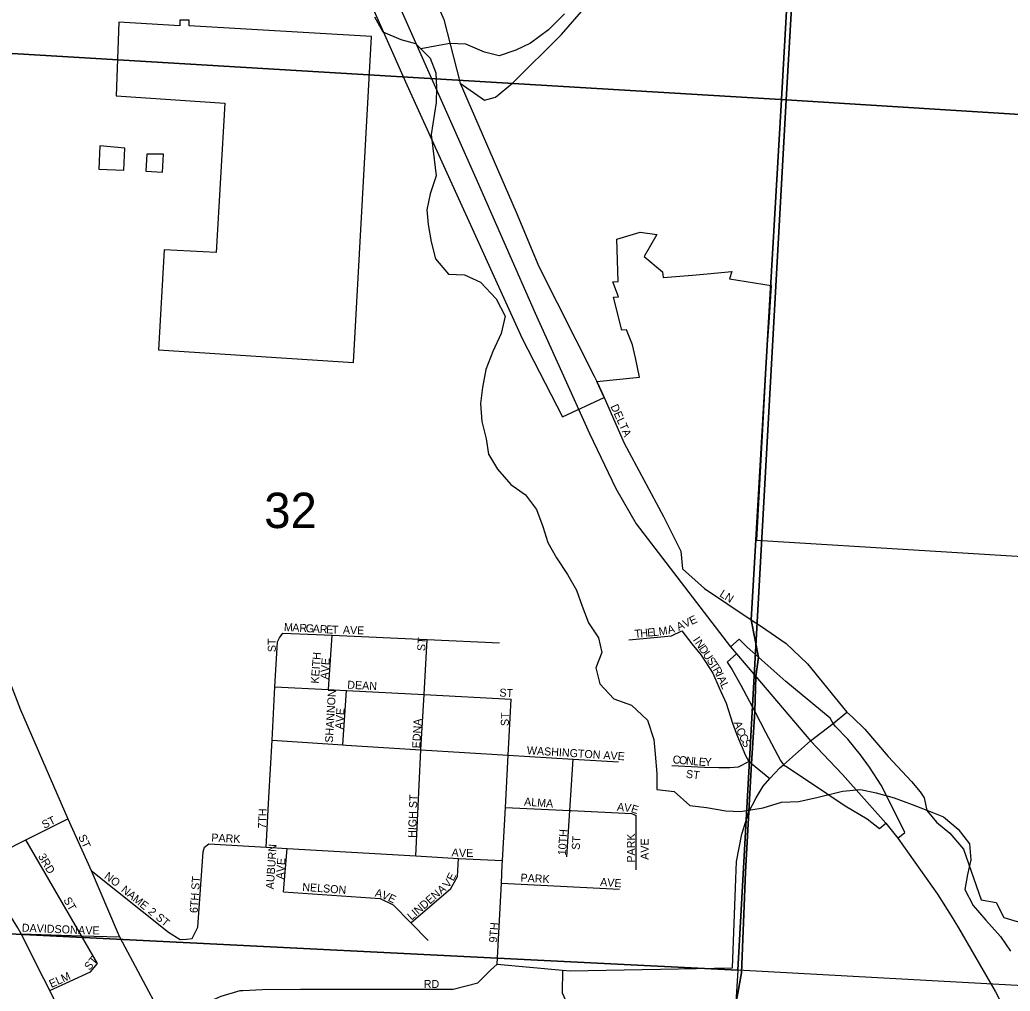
# Model space of a CAD drawing. Extents: x 1949938.81 to 1949945.61, y 152207.65 to 152214.09.
# Drawn here: x 1949940.427 to 1949941.599, y 152209.158 to 152210.308 of the extents above; entities that cross this region are included whole.
import ezdxf

# ---------------------------------------------------------------- set-up
doc = ezdxf.new("R2010")
doc.units = 0
for name, color, linetype in [('GM_X_City_Street', 7, 'Continuous'), ('GM_X_City_Street_Text', 7, 'Continuous'), ('GM_X_Corporation', 7, 'Continuous'), ('GM_X_County_Road', 7, 'Continuous'), ('GM_X_Interchange_Ramps', 7, 'Continuous'), ('GM_X_Minor_River', 7, 'Continuous'), ('GM_X_Section', 7, 'Continuous'), ('GM_X_Section_Text', 7, 'Continuous'), ('GM_X_Township', 7, 'Continuous'), ('GM_X_Township_Road', 7, 'Continuous'), ('GM_X_US_Route', 7, 'Continuous')]:
    doc.layers.add(name, color=color, linetype=linetype)

msp = doc.modelspace()

# ---------------------------------------------------------------- linework, layer by layer
at = {"layer": 'GM_X_City_Street'}
for points in [[(1949941.1155, 152209.8678), (1949941.1187, 152209.8607), (1949941.1424, 152209.8068), (1949941.1891, 152209.72), (1949941.2095, 152209.679), (1949941.2114, 152209.6583), (1949941.2375, 152209.6347), (1949941.2927, 152209.598), (1949941.3038, 152209.5906), (1949941.3341, 152209.5697), (1949941.3595, 152209.5458), (1949941.4062, 152209.4887)], [(1949940.3073, 152209.828), (1949940.3099, 152209.8198), (1949940.3687, 152209.6481), (1949940.3953, 152209.5754), (1949940.428, 152209.4915), (1949940.4841, 152209.3624), (1949940.5115, 152209.3013), (1949940.5424, 152209.2289)], [(1949940.722, 152209.3876), (1949940.722, 152209.3877), (1949940.7258, 152209.4553), (1949940.7292, 152209.5187), (1949940.7322, 152209.5719), (1949940.7345, 152209.5764), (1949940.7384, 152209.5821)], [(1949940.7384, 152209.5821), (1949940.7778, 152209.5803), (1949940.7778, 152209.5803)], [(1949941.1694, 152209.5761), (1949941.1986, 152209.5789), (1949941.2107, 152209.5846)], [(1949941.2107, 152209.5846), (1949941.2225, 152209.5695), (1949941.2336, 152209.5561), (1949941.2475, 152209.5346), (1949941.2548, 152209.5174), (1949941.2631, 152209.4991), (1949941.2707, 152209.4754), (1949941.2757, 152209.4616), (1949941.286, 152209.4373), (1949941.2901, 152209.4302), (1949941.293, 152209.4279), (1949941.3147, 152209.4102)], [(1949940.7778, 152209.5803), (1949940.7971, 152209.5795), (1949940.9092, 152209.5745), (1949940.9949, 152209.5706)], [(1949940.7924, 152209.5154), (1949940.7971, 152209.5795)], [(1949940.902, 152209.444), (1949940.9056, 152209.5094), (1949940.9092, 152209.5745)], [(1949941.1481, 152209.5741), (1949941.1694, 152209.5761)], [(1949941.4126, 152209.4825), (1949941.4273, 152209.4684), (1949941.4548, 152209.436), (1949941.4824, 152209.4065), (1949941.4928, 152209.3941), (1949941.4976, 152209.3871), (1949941.5005, 152209.3722), (1949941.5121, 152209.3585), (1949941.528, 152209.3455), (1949941.544, 152209.3266), (1949941.5648, 152209.2665), (1949941.5827, 152209.2632), (1949941.592, 152209.2455), (1949941.6075, 152209.2407), (1949941.6263, 152209.2428), (1949941.6379, 152209.251), (1949941.6564, 152209.2608), (1949941.6746, 152209.2817), (1949941.6788, 152209.3083), (1949941.6833, 152209.3542), (1949941.689, 152209.3706), (1949941.7068, 152209.4032), (1949941.7925, 152209.5244), (1949941.7945, 152209.5273)], [(1949940.7292, 152209.5187), (1949940.7924, 152209.5154), (1949940.7992, 152209.515)], [(1949940.7992, 152209.515), (1949940.7992, 152209.515), (1949940.8137, 152209.5143), (1949940.9056, 152209.5094), (1949941.0089, 152209.5039)], [(1949940.8096, 152209.4499), (1949940.8137, 152209.5143)], [(1949940.9983, 152209.3079), (1949940.9986, 152209.3132), (1949941.002, 152209.3759), (1949941.0053, 152209.4377), (1949941.0089, 152209.5039)], [(1949941.3897, 152209.4752), (1949941.4062, 152209.4887), (1949941.4126, 152209.4825)], [(1949941.3698, 152209.4596), (1949941.3897, 152209.4752)], [(1949940.7258, 152209.4553), (1949940.8096, 152209.4499), (1949940.8134, 152209.4497), (1949940.8136, 152209.4497)], [(1949941.2748, 152209.2912), (1949941.2756, 152209.312), (1949941.2818, 152209.3443), (1949941.2899, 152209.3706), (1949941.2986, 152209.3871), (1949941.3071, 152209.4008), (1949941.3147, 152209.4102), (1949941.3267, 152209.4227), (1949941.331, 152209.4264), (1949941.3632, 152209.4545), (1949941.3698, 152209.4596)], [(1949940.8136, 152209.4497), (1949940.902, 152209.444), (1949941.0053, 152209.4377), (1949941.082, 152209.4331), (1949941.1358, 152209.4298)], [(1949940.8961, 152209.3185), (1949940.902, 152209.444)], [(1949941.0745, 152209.3173), (1949941.078, 152209.3723), (1949941.082, 152209.4331)], [(1949941.2545, 152209.4232), (1949941.2675, 152209.4231), (1949941.2779, 152209.424), (1949941.2901, 152209.4302)], [(1949941.1988, 152209.4255), (1949941.2377, 152209.4233), (1949941.2545, 152209.4232)], [(1949940.7188, 152209.3287), (1949940.722, 152209.3876)], [(1949941.002, 152209.3759), (1949941.078, 152209.3723), (1949941.0796, 152209.3722), (1949941.0796, 152209.3722)], [(1949941.0796, 152209.3722), (1949941.1513, 152209.3688), (1949941.1566, 152209.3661)], [(1949940.3786, 152209.3094), (1949940.4345, 152209.3375), (1949940.4841, 152209.3624)], [(1949941.1566, 152209.3019), (1949941.1566, 152209.3661)], [(1949940.5002, 152209.224), (1949940.4345, 152209.3375)], [(1949940.6247, 152209.2201), (1949940.6312, 152209.2208), (1949940.6378, 152209.234), (1949940.6442, 152209.3233), (1949940.6458, 152209.3289)], [(1949940.6458, 152209.3289), (1949940.6508, 152209.3327), (1949940.7188, 152209.3287), (1949940.7435, 152209.3273), (1949940.8961, 152209.3185), (1949940.9463, 152209.3156), (1949940.9986, 152209.3132)], [(1949940.7395, 152209.2761), (1949940.7435, 152209.3273)], [(1949940.8899, 152209.2393), (1949940.9375, 152209.2798), (1949940.9453, 152209.2942), (1949940.9463, 152209.3156)], [(1949940.4828, 152209.1185), (1949940.4627, 152209.1592), (1949940.4558, 152209.1732), (1949940.4287, 152209.2261), (1949940.4251, 152209.2332), (1949940.3975, 152209.2768), (1949940.3786, 152209.3094)], [(1949940.5115, 152209.3013), (1949940.6032, 152209.2284), (1949940.6171, 152209.2195), (1949940.6247, 152209.2201)], [(1949940.992, 152209.1902), (1949940.9972, 152209.2864), (1949940.9983, 152209.3079), (1949940.9983, 152209.3079)], [(1949940.6913, 152209.1593), (1949940.7145, 152209.1603), (1949940.7595, 152209.1607), (1949940.9401, 152209.1606), (1949940.9693, 152209.1682), (1949940.9844, 152209.1834), (1949940.992, 152209.1902), (1949941.0694, 152209.1834), (1949941.0787, 152209.1826), (1949941.2707, 152209.1859), (1949941.2748, 152209.2912)], [(1949940.9972, 152209.2864), (1949941.137, 152209.2793)], [(1949940.7395, 152209.2761), (1949940.8539, 152209.2679), (1949940.869, 152209.2605), (1949940.8899, 152209.2393), (1949940.9106, 152209.2182)], [(1949940.4287, 152209.2261), (1949940.5002, 152209.224), (1949940.5451, 152209.2227)], [(1949940.5193, 152209.191), (1949940.5002, 152209.224)], [(1949940.5424, 152209.2289), (1949940.5451, 152209.2227), (1949940.5948, 152209.1297), (1949940.5981, 152209.1219)], [(1949940.4627, 152209.1592), (1949940.5109, 152209.1812), (1949940.5193, 152209.191)], [(1949941.0694, 152209.1834), (1949941.0691, 152209.1566), (1949941.0772, 152209.1391), (1949941.1035, 152209.1159), (1949941.1339, 152209.0939), (1949941.1516, 152209.0857), (1949941.1711, 152209.0843), (1949941.1873, 152209.0832), (1949941.2206, 152209.0808), (1949941.2628, 152209.0777), (1949941.2661, 152209.0775)], [(1949940.5981, 152209.1219), (1949940.627, 152209.1354), (1949940.6657, 152209.1525), (1949940.6882, 152209.1592), (1949940.6913, 152209.1593)]]:
    msp.add_lwpolyline(points, dxfattribs=at)
at = {"layer": 'GM_X_Corporation'}
msp.add_lwpolyline([(1949940.8339, 152210.3468), (1949940.8851, 152210.231), (1949941.0217, 152209.9309), (1949941.0697, 152209.8379), (1949941.1187, 152209.8607), (1949941.1101, 152209.88), (1949941.1608, 152209.8849), (1949941.1558, 152209.9078), (1949941.1522, 152209.9233), (1949941.1454, 152209.941), (1949941.1397, 152209.9406), (1949941.13, 152209.9796), (1949941.1357, 152209.98), (1949941.1289, 152209.9978), (1949941.1355, 152209.9983), (1949941.1338, 152210.0482), (1949941.1615, 152210.0567), (1949941.1812, 152210.0539), (1949941.1661, 152210.0278), (1949941.188, 152210.0094), (1949941.1885, 152210.0028), (1949941.2234, 152210.0058), (1949941.2406, 152210.0073), (1949941.2698, 152210.0099), (1949941.267, 152210.0014), (1949941.3166, 152209.9936), (1949941.3139, 152209.955), (1949941.3114, 152209.9182), (1949941.299, 152209.692), (1949941.7101, 152209.6669)], dxfattribs=at)
for points in [[(1949940.5446, 152210.3052), (1949940.5412, 152210.218), (1949940.67, 152210.209), (1949940.6596, 152210.0323), (1949940.5979, 152210.0357), (1949940.5915, 152209.9173), (1949940.8223, 152209.9024), (1949940.8435, 152210.2879), (1949940.6278, 152210.3005), (1949940.6275, 152210.3074), (1949940.6166, 152210.3075), (1949940.6165, 152210.3008)], [(1949940.5219, 152210.1588), (1949940.5207, 152210.1311), (1949940.5502, 152210.13), (1949940.5517, 152210.1561)], [(1949940.5764, 152210.1289), (1949940.5962, 152210.1274), (1949940.5973, 152210.149), (1949940.5775, 152210.149)]]:
    msp.add_lwpolyline(points, close=True, dxfattribs=at)
at = {"layer": 'GM_X_County_Road'}
for points in [[(1949940.6238, 152210.9905), (1949940.7663, 152210.6357), (1949940.884, 152210.3789), (1949940.9129, 152210.3457), (1949940.9292, 152210.3083), (1949940.9485, 152210.2329)], [(1949940.9485, 152210.2329), (1949941.0146, 152210.0802), (1949941.0415, 152210.0159), (1949941.1071, 152209.886)], [(1949941.1071, 152209.886), (1949941.1101, 152209.88), (1949941.1155, 152209.8678)]]:
    msp.add_lwpolyline(points, dxfattribs=at)
at = {"layer": 'GM_X_Interchange_Ramps'}
for points in [[(1949941.3897, 152209.4752), (1949941.3861, 152209.4813), (1949941.334, 152209.5247), (1949941.3053, 152209.5502), (1949941.3013, 152209.5538), (1949941.2882, 152209.5653), (1949941.2787, 152209.5748), (1949941.2684, 152209.5658)], [(1949941.2755, 152209.5576), (1949941.2643, 152209.5479), (1949941.27, 152209.5396), (1949941.2805, 152209.5207), (1949941.2971, 152209.4892), (1949941.3099, 152209.4648), (1949941.3274, 152209.4314), (1949941.331, 152209.4264)], [(1949941.4662, 152209.3396), (1949941.4746, 152209.3462), (1949941.4638, 152209.3687), (1949941.4467, 152209.4021), (1949941.4328, 152209.4233), (1949941.4221, 152209.4382), (1949941.4071, 152209.4565), (1949941.3926, 152209.4716), (1949941.3897, 152209.4752)], [(1949941.331, 152209.4264), (1949941.3359, 152209.4235), (1949941.3825, 152209.3925), (1949941.4042, 152209.3777), (1949941.43, 152209.3624), (1949941.4447, 152209.3508), (1949941.452, 152209.3572)]]:
    msp.add_lwpolyline(points, dxfattribs=at)
at = {"layer": 'GM_X_Minor_River'}
for points in [[(1949940.8471, 152210.3113), (1949940.8569, 152210.2937), (1949940.878, 152210.2845), (1949940.8954, 152210.2799), (1949940.9128, 152210.2624), (1949940.9195, 152210.2449), (1949940.9202, 152210.2274), (1949940.9201, 152210.2099), (1949940.9139, 152210.1719), (1949940.9176, 152210.143), (1949940.9198, 152210.1232), (1949940.9129, 152210.1019), (1949940.909, 152210.0829), (1949940.9105, 152210.0654), (1949940.9142, 152210.0449), (1949940.9194, 152210.0251), (1949940.9345, 152210.0068), (1949940.9534, 152210.006), (1949940.9723, 152209.9975), (1949940.9911, 152209.9777), (1949941.0017, 152209.9571), (1949940.997, 152209.9366), (1949940.9871, 152209.9154), (1949940.9787, 152209.8941), (1949940.9748, 152209.8728), (1949940.9725, 152209.8538), (1949940.9739, 152209.8325), (1949940.9791, 152209.812), (1949940.9821, 152209.7937), (1949940.9926, 152209.7762), (1949941.0084, 152209.7579), (1949941.0258, 152209.7457), (1949941.0386, 152209.7282), (1949941.0461, 152209.7084), (1949941.0521, 152209.6894), (1949941.0626, 152209.6711), (1949941.0754, 152209.6513), (1949941.0859, 152209.633), (1949941.0926, 152209.614), (1949941.1001, 152209.5942), (1949941.1122, 152209.5767), (1949941.1159, 152209.5592), (1949941.109, 152209.541), (1949941.1135, 152209.522), (1949941.1301, 152209.5044), (1949941.1512, 152209.4968), (1949941.1701, 152209.4792), (1949941.1776, 152209.4564), (1949941.179, 152209.4389), (1949941.1812, 152209.4161), (1949941.1811, 152209.3971), (1949941.2016, 152209.3948), (1949941.2204, 152209.378), (1949941.2401, 152209.3756), (1949941.2628, 152209.3718), (1949941.2802, 152209.3709), (1949941.3068, 152209.3754), (1949941.3288, 152209.3822), (1949941.3492, 152209.3829), (1949941.3719, 152209.3881), (1949941.4008, 152209.3949), (1949941.422, 152209.3971), (1949941.4409, 152209.3932), (1949941.4621, 152209.3871), (1949941.4833, 152209.3794), (1949941.5006, 152209.3725), (1949941.5203, 152209.3648), (1949941.5377, 152209.3503), (1949941.5512, 152209.3328), (1949941.5527, 152209.3138), (1949941.5488, 152209.2964), (1949941.5457, 152209.2789), (1949941.5555, 152209.2599), (1949941.5705, 152209.2423), (1949941.5879, 152209.2233), (1949941.5999, 152209.2058)], [(1949941.072, 152210.315), (1949941.053, 152210.2961), (1949941.0317, 152210.2802), (1949941.0143, 152210.2719), (1949940.9946, 152210.2651), (1949940.9772, 152210.2697), (1949940.9552, 152210.2789), (1949940.9363, 152210.2798), (1949940.9189, 152210.2768), (1949940.9018, 152210.2734)]]:
    msp.add_lwpolyline(points, dxfattribs=at)
at = {"layer": 'GM_X_Section'}
for points in [[(1949941.3926, 152211.2226), (1949941.3344, 152210.2133), (1949940.227, 152210.2792), (1949940.2943, 152211.2945)], [(1949942.4891, 152211.1555), (1949942.4221, 152210.1447), (1949941.3344, 152210.2133), (1949941.3926, 152211.2226)], [(1949940.227, 152210.2792), (1949941.3344, 152210.2133), (1949941.2772, 152209.1831), (1949940.3437, 152209.23), (1949940.3324, 152209.2952), (1949940.3195, 152209.3183), (1949940.3078, 152209.3429), (1949940.3025, 152209.3539), (1949940.2934, 152209.3725), (1949940.2828, 152209.3933), (1949940.2737, 152209.4089), (1949940.2662, 152209.4206), (1949940.2575, 152209.4339), (1949940.248, 152209.4483), (1949940.2389, 152209.4665), (1949940.2332, 152209.476), (1949940.2245, 152209.4885), (1949940.1749, 152209.5309)], [(1949941.3344, 152210.2133), (1949942.4221, 152210.1447), (1949942.3551, 152209.1241), (1949941.2772, 152209.1831)]]:
    msp.add_lwpolyline(points, close=True, dxfattribs=at)
msp.add_lwpolyline([(1949940.4149, 152209.1481), (1949940.4062, 152209.1614), (1949940.3994, 152209.172), (1949940.3948, 152209.1796), (1949940.3922, 152209.1841), (1949940.3437, 152209.23), (1949941.2772, 152209.1831), (1949941.2271, 152208.3769)], dxfattribs=at)
at = {"layer": 'GM_X_Township'}
for points in [[(1949941.4472, 152212.2194), (1949941.3847, 152211.2124), (1949941.3503, 152210.5979), (1949941.3284, 152210.2069), (1949941.2927, 152209.598), (1949941.3013, 152209.5538), (1949941.2985, 152209.5306), (1949941.2971, 152209.4892), (1949941.293, 152209.4279), (1949941.2903, 152209.3782), (1949941.2899, 152209.3706), (1949941.286, 152209.2993), (1949941.2812, 152209.1802), (1949941.2628, 152209.0777)], [(1949941.2628, 152209.0777), (1949941.2812, 152209.1802), (1949941.286, 152209.2993), (1949941.2899, 152209.3706), (1949941.2903, 152209.3782), (1949941.293, 152209.4279), (1949941.2971, 152209.4892), (1949941.2985, 152209.5306), (1949941.3013, 152209.5538), (1949941.2927, 152209.598), (1949941.3284, 152210.2069), (1949941.3503, 152210.5979), (1949941.3847, 152211.2124), (1949941.4472, 152212.2194)]]:
    msp.add_lwpolyline(points, dxfattribs=at)
at = {"layer": 'GM_X_Township_Road'}
msp.add_lwpolyline([(1949940.9485, 152210.2329), (1949940.9773, 152210.2129), (1949940.9902, 152210.2163), (1949941.0103, 152210.233), (1949941.0683, 152210.2904), (1949941.1156, 152210.3451), (1949941.141, 152210.3748), (1949941.1584, 152210.3881), (1949941.1853, 152210.4177), (1949941.2008, 152210.4352), (1949941.2088, 152210.4455), (1949941.2186, 152210.4846), (1949941.2243, 152210.4994), (1949941.2539, 152210.5317), (1949941.2664, 152210.5382), (1949941.2895, 152210.5439), (1949941.3046, 152210.5572), (1949941.3405, 152210.5899)], dxfattribs=at)
at = {"layer": 'GM_X_US_Route'}
for points in [[(1949940.448, 152211.375), (1949940.4583, 152211.3469), (1949940.5043, 152211.2261), (1949940.5628, 152211.0708), (1949940.5921, 152210.9937), (1949940.6917, 152210.7462), (1949940.7773, 152210.5432), (1949940.8719, 152210.3344), (1949940.9687, 152210.1169), (1949941.0372, 152209.9608), (1949941.0687, 152209.891)], [(1949941.0687, 152209.891), (1949941.1015, 152209.8181), (1949941.1326, 152209.7532), (1949941.1566, 152209.7115), (1949941.2008, 152209.6539)], [(1949941.2008, 152209.6539), (1949941.2684, 152209.5658), (1949941.2755, 152209.5576), (1949941.2985, 152209.5306), (1949941.3632, 152209.4545), (1949941.4009, 152209.4149), (1949941.452, 152209.3572), (1949941.4662, 152209.3396), (1949941.5132, 152209.2733), (1949941.5294, 152209.2477)], [(1949941.5294, 152209.2477), (1949941.5383, 152209.2335), (1949941.5818, 152209.1576), (1949941.6123, 152209.0983), (1949941.6342, 152209.0601), (1949941.6685, 152209.0062), (1949941.6823, 152208.9876), (1949941.7205, 152208.9478), (1949941.7486, 152208.9239), (1949941.7741, 152208.9085), (1949941.8038, 152208.8936), (1949941.8357, 152208.8798), (1949941.9137, 152208.8506), (1949941.9801, 152208.8272), (1949942.0156, 152208.8118), (1949942.0491, 152208.7911), (1949942.1538, 152208.692), (1949942.266, 152208.5946), (1949942.3472, 152208.5215)]]:
    msp.add_lwpolyline(points, dxfattribs=at)

# ---------------------------------------------------------------- texts
at = {"layer": 'GM_X_City_Street_Text'}
for s, rotation, p in [('DELTA', 294.3422, (1949941.1261, 152209.8504)), ('LN', 327.9928, (1949941.2546, 152209.6261)), ('M', 356.6941, (1949940.7396, 152209.5847)), ('A', 356.696, (1949940.7495, 152209.5842)), ('A', 24.7745, (1949941.207, 152209.5846)), ('V', 24.7745, (1949941.2146, 152209.5881)), ('E', 24.7745, (1949941.2222, 152209.5916)), ('R', 356.6925, (1949940.7579, 152209.5837)), ('G', 356.696, (1949940.7654, 152209.5833)), ('A', 356.696, (1949940.7737, 152209.5828)), ('R', 356.6925, (1949940.782, 152209.5823)), ('E', 357.1073, (1949940.7896, 152209.5819)), ('T', 359.2995, (1949940.7966, 152209.5815)), ('AVE', 358.0247, (1949940.8095, 152209.5814)), ('T', 5.3894, (1949941.1552, 152209.5765)), ('H', 5.3894, (1949941.1619, 152209.5771)), ('E', 5.3894, (1949941.1702, 152209.5779)), ('L', 5.3894, (1949941.1768, 152209.5785)), ('M', 8.6203, (1949941.184, 152209.5792)), ('A', 15.0819, (1949941.195, 152209.581)), ('ST', 90, (1949940.7302, 152209.5596)), ('ST', 86.4256, (1949940.9069, 152209.5606)), ('I', 303.9431, (1949941.2234, 152209.574)), ('N', 303.9227, (1949941.2258, 152209.5705)), ('KEITH', 85.9166, (1949940.781, 152209.5221)), ('D', 303.925, (1949941.2304, 152209.5636)), ('U', 303.9251, (1949941.2351, 152209.5567)), ('AVE', 86.057, (1949940.7923, 152209.5271)), ('S', 303.9361, (1949941.2397, 152209.5498)), ('T', 303.9155, (1949941.2434, 152209.5442)), ('R', 299.7562, (1949941.2471, 152209.5389)), ('I', 295.1965, (1949941.2507, 152209.5325)), ('DEAN', 357.0643, (1949940.8146, 152209.5164)), ('A', 294.833, (1949941.2525, 152209.5288)), ('L', 294.778, (1949941.256, 152209.5212)), ('SHANNON', 86.6354, (1949940.7977, 152209.4521)), ('ST', 356.4228, (1949940.9946, 152209.5072)), ('AVE', 86.057, (1949940.8098, 152209.468)), ('ST', 90, (1949941.006, 152209.4721)), ('EDNA', 87.0659, (1949940.901, 152209.4456)), ('A', 289.6134, (1949941.272, 152209.4761)), ('C', 291.3984, (1949941.2749, 152209.4679)), ('C', 295.8926, (1949941.278, 152209.4602)), ('S', 296.5582, (1949941.2813, 152209.4533)), ('WASHINGTON AVE', 356.3669, (1949941.0271, 152209.4389)), ('C', 355.0635, (1949941.1996, 152209.4281)), ('O', 355.057, (1949941.2071, 152209.4274)), ('N', 355.0689, (1949941.2154, 152209.4267)), ('L', 355.0616, (1949941.2237, 152209.426)), ('E', 355.7329, (1949941.2305, 152209.4254)), ('Y', 359.0483, (1949941.2377, 152209.4249)), ('ST', 352.8767, (1949941.2152, 152209.4111)), ('HIGH ST', 87.876, (1949940.896, 152209.3397)), ('ALMA', 355.8151, (1949941.0238, 152209.3781)), ('7TH', 87.7106, (1949940.7185, 152209.3505)), ('A', 353.4186, (1949941.1337, 152209.3722)), ('V', 353.4199, (1949941.142, 152209.3713)), ('E', 342.7503, (1949941.1498, 152209.3704)), ('ST', 26.565, (1949940.4562, 152209.3504)), ('10TH', 86.4256, (1949941.0735, 152209.3189)), ('ST', 295.017, (1949940.4961, 152209.3412)), ('PARK', 356.9057, (1949940.6537, 152209.3356)), ('ST', 86.4256, (1949941.0898, 152209.3254)), ('PARK', 90, (1949941.1552, 152209.3105)), ('AVE', 90, (1949941.1715, 152209.3138)), ('AUBURN', 86.1236, (1949940.7277, 152209.2788)), ('A', 355.3167, (1949940.938, 152209.3181)), ('V', 359.2728, (1949940.947, 152209.3174)), ('E', 359.9999, (1949940.9555, 152209.3173)), ('3RD', 300.5801, (1949940.4485, 152209.318)), ('AVE', 86.057, (1949940.7398, 152209.2905)), ('NO', 323.1285, (1949940.5264, 152209.2927)), ('6TH ST', 86.188, (1949940.6377, 152209.2506)), ('V', 53.3567, (1949940.9344, 152209.2798)), ('E', 62.6816, (1949940.9402, 152209.288)), ('PARK', 356.906, (1949941.0196, 152209.2881)), ('AVE', 355.9142, (1949941.1138, 152209.2831)), ('NAME', 321.1172, (1949940.5464, 152209.2769)), ('NELSON', 355.8402, (1949940.7613, 152209.2772)), ('A', 348.0753, (1949940.847, 152209.2706)), ('V', 336.0064, (1949940.8546, 152209.269)), ('LINDEN', 41.0806, (1949940.8908, 152209.2418)), ('A', 38.1704, (1949940.9259, 152209.2727)), ('ST', 299.7432, (1949940.4785, 152209.2664)), ('E', 333.435, (1949940.8621, 152209.2657)), ('2', 315.0068, (1949940.5782, 152209.2517)), ('ST', 320.1969, (1949940.5873, 152209.2443)), ('DAVIDSON', 357.6467, (1949940.4295, 152209.2289)), ('A', 355.2182, (1949940.4958, 152209.2264)), ('V', 359.6386, (1949940.5049, 152209.2256)), ('E', 359.9985, (1949940.5133, 152209.2256)), ('9TH', 85.4285, (1949940.9919, 152209.2156)), ('ST', 50.1886, (1949940.5098, 152209.1824)), ('ELM', 24.7772, (1949940.4646, 152209.1621)), ('RD', 0, (1949940.9053, 152209.1622))]:
    msp.add_text(s, height=0.00947, rotation=rotation, dxfattribs=at).set_placement(p)
at = {"layer": 'GM_X_Section_Text'}
msp.add_text('32', height=0.04186, rotation=0, dxfattribs=at).set_placement((1949940.7165, 152209.7064))

doc.saveas('drawing.dxf')
